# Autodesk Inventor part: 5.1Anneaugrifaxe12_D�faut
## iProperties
Created: 2011-01
Part Number: 5.1Anneaugrifaxe12_D�faut
Document SubType Name: Modeling
Designer: eric
Density: 1 g/cm^3
Mass: 0.183487 g
Surface Area: 9.77041 cm^2
Volume: 0.183487 cm^3
Author: eric
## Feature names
1. Base1
